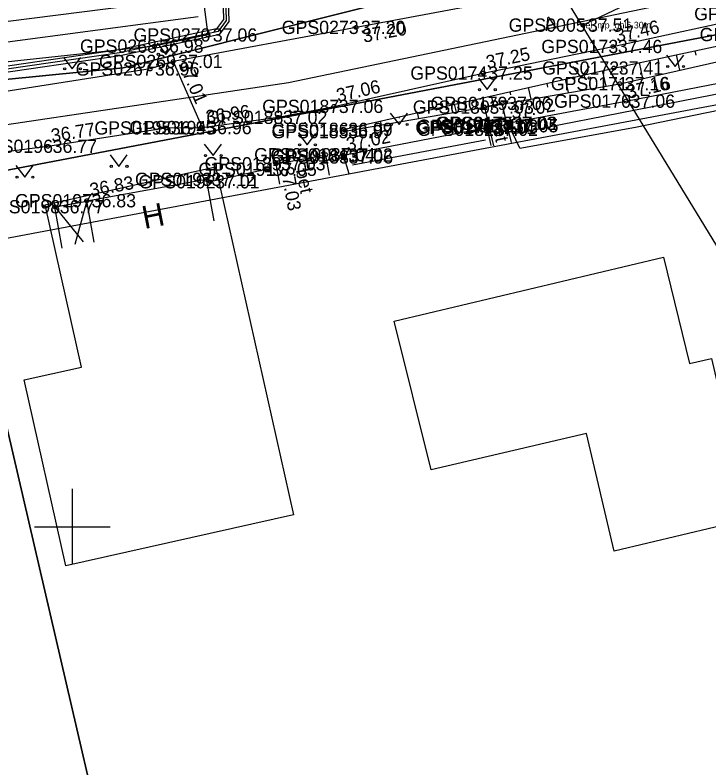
# Model space of a CAD drawing. Extents: x 626224 to 628280, y 6467750 to 6471135.
# Drawn here: x 627646.98 to 627683.58, y 6468587.27 to 6468627 of the extents above; entities that cross this region are included whole.
import ezdxf

# ---------------------------------------------------------------- set-up
doc = ezdxf.new("R2010")
doc.units = 0
for name, color, linetype in [('AED', 7, 'Continuous'), ('HALJASTUS', 7, 'Continuous'), ('HOONE', 7, 'Continuous'), ('Hoone Elu- või ühiskondlik hoone', 7, 'Continuous'), ('Hoone Kõrval- või tootmishoone', 7, 'Continuous'), ('HOONEDET', 7, 'Continuous'), ('KORGUS-EH2000', 7, 'Continuous'), ('KPKAABEL', 7, 'Continuous'), ('MAAMUDEL', 7, 'Continuous'), ('MOOTKORG-EH2000', 7, 'Continuous'), ('MOOTMPUNKT', 7, 'Continuous'), ('MOOTNR', 7, 'Continuous'), ('MOOTPIIR', 7, 'Continuous'), ('MPKAABEL', 7, 'Continuous'), ('MPOHULIIN', 7, 'Continuous'), ('PIIR', 7, 'Continuous'), ('RELJEEF', 7, 'Continuous'), ('TEE', 7, 'Continuous'), ('Tee Muu tee Kruuskate', 7, 'Continuous'), ('Tee Muu tee Püsikate', 7, 'Continuous'), ('VORK', 7, 'Continuous')]:
    doc.layers.add(name, color=color, linetype=linetype)

msp = doc.modelspace()

# ---------------------------------------------------------------- linework, layer by layer
at = {"layer": 'AED'}
for p, q in [((627671.829, 6468621.099), (627671.829, 6468620.849)), ((627671.829, 6468621.099), (627672.079, 6468621.099)), ((627672.079, 6468621.099), (627672.079, 6468620.849)), ((627672.91, 6468621.284), (627672.91, 6468621.034)), ((627672.91, 6468621.284), (627673.16, 6468621.284)), ((627672.91, 6468621.034), (627673.16, 6468621.034)), ((627673.16, 6468621.284), (627673.16, 6468621.034)), ((627671.829, 6468620.849), (627672.079, 6468620.849)), ((627664.186, 6468619.637), (627664.186, 6468619.387)), ((627664.186, 6468619.637), (627664.436, 6468619.637)), ((627664.436, 6468619.637), (627664.436, 6468619.387)), ((627664.186, 6468619.387), (627664.436, 6468619.387)), ((627660.291, 6468618.862), (627657.113, 6468618.168)), ((627660.166, 6468618.987), (627660.166, 6468618.737)), ((627660.166, 6468618.987), (627660.416, 6468618.987)), ((627660.166, 6468618.737), (627660.416, 6468618.737)), ((627660.416, 6468618.987), (627660.416, 6468618.737))]:
    msp.add_line(p, q, dxfattribs=at)
at = {"layer": 'HALJASTUS'}
for p, q in [((627637.187, 6468624.338), (627656.639, 6468626.929)), ((627654.473, 6468625.531), (627654.937, 6468624.925)), ((627654.937, 6468624.925), (627655.382, 6468625.531)), ((627649.535, 6468624.768), (627649.998, 6468624.161)), ((627649.998, 6468624.161), (627650.444, 6468624.768)), ((627681.34, 6468624.889), (627681.803, 6468624.282)), ((627681.803, 6468624.282), (627682.249, 6468624.889)), ((627676.376, 6468624.287), (627676.84, 6468623.68)), ((627676.84, 6468623.68), (627677.285, 6468624.287)), ((627671.416, 6468623.671), (627671.88, 6468623.064)), ((627671.88, 6468623.064), (627672.325, 6468623.671)), ((627666.768, 6468621.827), (627667.232, 6468621.22)), ((627667.232, 6468621.22), (627667.677, 6468621.827)), ((627661.927, 6468620.755), (627662.391, 6468620.148)), ((627662.391, 6468620.148), (627662.836, 6468620.755)), ((627664.781, 6468619.103), (627671.798, 6468620.423)), ((627656.96, 6468620.189), (627657.423, 6468619.582)), ((627657.423, 6468619.582), (627657.869, 6468620.189)), ((627651.992, 6468619.623), (627652.455, 6468619.016)), ((627652.455, 6468619.016), (627652.901, 6468619.623)), ((627647.024, 6468619.057), (627647.487, 6468618.45)), ((627647.487, 6468618.45), (627647.933, 6468619.057))]:
    msp.add_line(p, q, dxfattribs=at)
for points in [[(627636.336, 6468625.375), (627656.875, 6468628.003), (627657.149, 6468625.947), (627654.322, 6468625.361), (627643.674, 6468624.206), (627636.948, 6468623.11), (627636.336, 6468625.375)], [(627673.61, 6468619.969), (627672.976, 6468621.286), (627679.187, 6468622.456), (627687.969, 6468624.157), (627689.948, 6468620.551), (627692.796, 6468621.064), (627698.292, 6468613.159), (627705.989, 6468601.538), (627717.166, 6468585.678)], [(627716.572, 6468584.873), (627705.028, 6468601.396), (627692.406, 6468620.356), (627689.621, 6468619.759), (627687.703, 6468623.543), (627673.321, 6468620.739)], [(627673.61, 6468619.969), (627679.701, 6468621.092), (627687.315, 6468622.642), (627689.297, 6468618.889), (627691.61, 6468619.392), (627696.609, 6468612.017), (627704.309, 6468600.39), (627715.503, 6468584.506)], [(627664.609, 6468618.629), (627664.298, 6468619.611), (627671.869, 6468621.074), (627672.073, 6468620.112)]]:
    msp.add_lwpolyline(points, dxfattribs=at)
for centre in [(627654.536, 6468624.925), (627655.364, 6468624.925), (627649.597, 6468624.161), (627650.426, 6468624.161), (627681.402, 6468624.282), (627682.231, 6468624.282), (627676.439, 6468623.68), (627677.267, 6468623.68), (627671.479, 6468623.064), (627672.307, 6468623.064), (627666.831, 6468621.22), (627667.66, 6468621.22), (627661.99, 6468620.148), (627662.819, 6468620.148), (627657.022, 6468619.582), (627657.851, 6468619.582), (627652.054, 6468619.016), (627652.883, 6468619.016), (627647.086, 6468618.45), (627647.915, 6468618.45)]:
    msp.add_circle(centre, 0.055, dxfattribs=at)
at = {"layer": 'HOONE'}
for p, q in [((627650.758, 6468617.203), (627657.084, 6468618.331)), ((627657.474, 6468616.146), (627657.084, 6468618.331)), ((627649.076, 6468616.886), (627650.761, 6468617.186)), ((627651.147, 6468615.018), (627650.758, 6468617.203)), ((627649.466, 6468614.701), (627649.076, 6468616.886))]:
    msp.add_line(p, q, dxfattribs=at)
at = {"layer": 'Hoone Elu- või ühiskondlik hoone'}
msp.add_lwpolyline([(627678.585, 6468598.716), (627677.114, 6468604.925), (627668.925, 6468602.995), (627666.971, 6468610.855), (627681.171, 6468614.225), (627682.555, 6468608.606), (627683.705, 6468608.876), (627685.675, 6468600.395)], close=True, dxfattribs=at)
at = {"layer": 'Hoone Kõrval- või tootmishoone'}
msp.add_lwpolyline([(627661.667, 6468600.628), (627649.66, 6468597.941), (627647.466, 6468607.745), (627650.484, 6468608.42), (627648.567, 6468616.984), (627657.556, 6468618.996)], close=True, dxfattribs=at)
at = {"layer": 'HOONEDET'}
for p, q in [((627650.758, 6468617.203), (627650.14, 6468614.889)), ((627649.076, 6468616.886), (627650.564, 6468615.033))]:
    msp.add_line(p, q, dxfattribs=at)
at = {"layer": 'KORGUS-EH2000'}
for centre in [(627664.963, 6468626.349), (627678.512, 6468625.342), (627655.323, 6468624.553), (627671.677, 6468623.939), (627678.877, 6468623.378), (627663.795, 6468622.181), (627656.855, 6468621.064), (627672.976, 6468621.286), (627648.701, 6468620.075), (627664.298, 6468619.611), (627660.755, 6468619.153), (627657.273, 6468618.203), (627650.758, 6468617.203)]:
    msp.add_circle(centre, 0.1, dxfattribs=at)
at = {"layer": 'KPKAABEL'}
msp.add_lwpolyline([(627685.782, 6468640.643), (627682.599, 6468638.441), (627678.043, 6468635.809), (627672.046, 6468634.344), (627660.214, 6468631.662), (627657.997, 6468630.954), (627658.117, 6468626.708), (627657.689, 6468626.13), (627652.495, 6468625.008), (627640.455, 6468623.259), (627628.481, 6468622.246), (627623.048, 6468622.007), (627612.632, 6468622.516), (627609.034, 6468622.858), (627605.474, 6468623.034), (627601.854, 6468622.409), (627599.956, 6468622.4), (627599.775, 6468623.347)], dxfattribs=at)
at = {"layer": 'MOOTMPUNKT'}
for centre in [(627664.963, 6468626.349), (627676.933, 6468626.469), (627676.933, 6468626.469), (627657.149, 6468625.947), (627654.322, 6468625.361), (627678.512, 6468625.342), (627655.323, 6468624.553), (627654.099, 6468624.153), (627678.559, 6468624.205), (627671.677, 6468623.939), (627678.877, 6468623.378), (627663.795, 6468622.181), (627671.739, 6468622.144), (627672.671, 6468622.34), (627679.187, 6468622.456), (627660.849, 6468621.603), (627654.943, 6468621.043), (627656.855, 6468621.064), (627664.293, 6468620.969), (627671.869, 6468621.074), (627671.954, 6468620.974), (627671.964, 6468621.133), (627672.925, 6468621.283), (627672.976, 6468621.286), (627673.035, 6468621.159), (627664.284, 6468620.85), (627648.701, 6468620.075), (627663.372, 6468619.631), (627664.298, 6468619.611), (627664.311, 6468619.512), (627660.755, 6468619.153), (627660.291, 6468618.862), (627657.084, 6468618.331), (627657.273, 6468618.203), (627650.758, 6468617.203), (627649.076, 6468616.886)]:
    msp.add_circle(centre, 0.1, dxfattribs=at)
at = {"layer": 'MOOTPIIR'}
msp.add_lwpolyline([(627644.92, 6468614.927), (627687.389, 6468622.904), (627689.377, 6468619.311), (627692.038, 6468619.76), (627702.956, 6468602.021), (627695.606, 6468595.477), (627701.992, 6468581.333), (627711.232, 6468581.738), (627717.166, 6468585.678), (627720.646, 6468589.364)], dxfattribs=at)
at = {"layer": 'MPKAABEL'}
for points in [[(627685.699, 6468640.768), (627682.519, 6468638.568), (627677.987, 6468635.95), (627672.012, 6468634.49), (627660.175, 6468631.807), (627657.844, 6468631.063), (627657.966, 6468626.756), (627657.602, 6468626.265), (627652.468, 6468625.156), (627640.438, 6468623.408), (627628.471, 6468622.396), (627623.048, 6468622.157), (627612.643, 6468622.666), (627609.045, 6468623.008), (627605.465, 6468623.185), (627601.841, 6468622.559), (627601.344, 6468627.176), (627599.992, 6468627.142), (627599.551, 6468626.364)], [(627599.73, 6468626.375), (627600.081, 6468626.994), (627601.209, 6468627.023), (627601.759, 6468622.259), (627605.483, 6468622.883), (627609.023, 6468622.708), (627612.621, 6468622.366), (627623.048, 6468621.857), (627628.491, 6468622.096), (627640.472, 6468623.11), (627652.522, 6468624.86), (627657.776, 6468625.995), (627658.268, 6468626.66), (627658.15, 6468630.845), (627660.253, 6468631.517), (627672.08, 6468634.198), (627673.058, 6468632.736)], [(627685.401, 6468627.702), (627679.495, 6468627.683), (627676.897, 6468626.445)]]:
    msp.add_lwpolyline(points, dxfattribs=at)
at = {"layer": 'MPOHULIIN'}
for points in [[(627679.915, 6468621.5), (627673.058, 6468632.736), (627672.71, 6468633.307)], [(627695.728, 6468595.585), (627679.915, 6468621.5)]]:
    msp.add_lwpolyline(points, dxfattribs=at)
at = {"layer": 'PIIR'}
for points in [[(627654.85, 6468663.52), (627663.66, 6468662.2), (627686.69, 6468632.75), (627684.35, 6468632.16), (627652.69, 6468624.22), (627623.24, 6468621.3), (627605.69, 6468621.95), (627588.94, 6468620.18), (627586.23, 6468625.97), (627596.31, 6468635.4), (627619.6, 6468659.76), (627624.98, 6468665.39), (627633.24, 6468674.95), (627637.73, 6468680.5), (627640.48, 6468683.65), (627644.86, 6468680.34)], [(627746.91, 6468541.23), (627666.94, 6468517.08), (627653, 6468577.43), (627643.52, 6468618.24), (627688.18, 6468626.77)], [(627599.49, 6468616.8), (627643.52, 6468618.24), (627653, 6468577.43), (627666.94, 6468517.08), (627608.44, 6468499.25), (627602.15, 6468514.88), (627588.44, 6468509.87), (627563.73, 6468583.75), (627555.29, 6468612.05)]]:
    msp.add_lwpolyline(points, close=True, dxfattribs=at)
msp.add_lwpolyline([(627401.5, 6468603.97), (627489.68, 6468613.41), (627577.55, 6468622.81), (627581.38, 6468622.85), (627583, 6468623.57), (627584.27, 6468624.13), (627586.23, 6468625.97), (627588.94, 6468620.18), (627605.69, 6468621.95), (627623.24, 6468621.3), (627652.69, 6468624.22), (627684.35, 6468632.16), (627688.18, 6468626.77), (627643.52, 6468618.24), (627599.49, 6468616.8), (627555.29, 6468612.05), (627411.34, 6468595.13)], dxfattribs=at)
at = {"layer": 'RELJEEF'}
for p, q in [((627682.835, 6468625.114), (627682.886, 6468624.874)), ((627680.878, 6468624.698), (627680.931, 6468624.45)), ((627681.856, 6468624.906), (627682.03, 6468624.092)), ((627678.922, 6468624.282), (627678.977, 6468624.026)), ((627679.9, 6468624.49), (627680.079, 6468623.65)), ((627676.971, 6468623.844), (627677.023, 6468623.614)), ((627677.946, 6468624.066), (627678.131, 6468623.249)), ((627675.995, 6468623.623), (627676.158, 6468622.907)), ((627674.045, 6468623.181), (627674.185, 6468622.565)), ((627675.02, 6468623.402), (627675.065, 6468623.202)), ((627672.094, 6468622.738), (627672.211, 6468622.223)), ((627673.07, 6468622.96), (627673.108, 6468622.79)), ((627670.144, 6468622.296), (627670.238, 6468621.882)), ((627671.119, 6468622.517), (627671.151, 6468622.378)), ((627668.194, 6468621.854), (627668.265, 6468621.54)), ((627669.169, 6468622.075), (627669.194, 6468621.966)), ((627667.218, 6468621.633), (627667.236, 6468621.553)), ((627665.268, 6468621.19), (627665.279, 6468621.141)), ((627666.243, 6468621.411), (627666.291, 6468621.198)), ((627664.293, 6468620.969), (627664.318, 6468620.856))]:
    msp.add_line(p, q, dxfattribs=at)
for points in [[(627664.293, 6468620.969), (627678.559, 6468624.205), (627686.866, 6468625.972), (627692.626, 6468627.53), (627694.391, 6468627.395), (627696.02, 6468626.757), (627697.766, 6468625.488), (627704.517, 6468617.101), (627712.652, 6468604.661), (627723.007, 6468591.238)], [(627664.284, 6468620.85), (627678.877, 6468623.378), (627691.199, 6468626.166), (627693.024, 6468626.089), (627694.96, 6468625.086), (627696.853, 6468623.559), (627702.288, 6468615.532), (627710.843, 6468603.567), (627720.646, 6468589.364)]]:
    msp.add_lwpolyline(points, dxfattribs=at)
at = {"layer": 'TEE'}
for p, q in [((627663.568, 6468618.555), (627663.372, 6468619.631)), ((627660.951, 6468618.078), (627660.755, 6468619.153))]:
    msp.add_line(p, q, dxfattribs=at)
for points in [[(627691.556, 6468636.216), (627691.411, 6468633.572), (627690.377, 6468632.362), (627688.302, 6468631.311), (627683.705, 6468630.285), (627675.534, 6468628.326), (627664.963, 6468626.349), (627655.323, 6468624.553), (627656.855, 6468621.064), (627660.849, 6468621.603), (627663.795, 6468622.181), (627671.677, 6468623.939), (627678.512, 6468625.342), (627686.437, 6468627.071), (627694.212, 6468628.779), (627696.498, 6468628.635), (627697.947, 6468628.287), (627705.762, 6468618.126), (627714.785, 6468606.184), (627724.497, 6468592.392)], [(627655.323, 6468624.553), (627654.099, 6468624.153), (627644.239, 6468622.621), (627634.78, 6468621.504), (627626.983, 6468620.991), (627620.731, 6468620.942), (627612.855, 6468621.244), (627605.321, 6468621.364)], [(627673.157, 6468620.276), (627672.925, 6468621.283), (627672.671, 6468622.34), (627671.739, 6468622.144), (627671.964, 6468621.133), (627672.206, 6468620.091)], [(627605.451, 6468618.323), (627611.844, 6468618.339), (627612.555, 6468616.606), (627613.007, 6468613.838), (627616.056, 6468613.833), (627615.95, 6468616.377), (627616.311, 6468617.523), (627617.098, 6468617.911), (627625.292, 6468617.768), (627631.755, 6468618.128), (627635.301, 6468618.359), (627643.867, 6468619.473), (627648.701, 6468620.075), (627654.943, 6468621.043), (627656.855, 6468621.064)], [(627660.755, 6468619.153), (627663.372, 6468619.631)]]:
    msp.add_lwpolyline(points, dxfattribs=at)
at = {"layer": 'Tee Muu tee Kruuskate'}
msp.add_lwpolyline([(627655.281, 6468622.513), (627643.219, 6468620.707), (627634.046, 6468619.94), (627621.905, 6468619.252), (627606.783, 6468619.17), (627583.198, 6468617.485), (627569.985, 6468616.221), (627554.678, 6468614.391), (627502.881, 6468608.768), (627472.157, 6468604.735), (627458.252, 6468603.133), (627409.627, 6468597.894), (627406.06, 6468597.51)], dxfattribs=at)
at = {"layer": 'Tee Muu tee Püsikate'}
msp.add_lwpolyline([(627700.902, 6468634.138), (627694.794, 6468631.457), (627685.552, 6468628.47), (627661.394, 6468623.428), (627655.281, 6468622.513)], dxfattribs=at)
at = {"layer": 'VORK'}
for p, q in [((627650, 6468602), (627650, 6468598)), ((627648, 6468600), (627652, 6468600))]:
    msp.add_line(p, q, dxfattribs=at)

# ---------------------------------------------------------------- texts
at = {"layer": 'HOONE'}
msp.add_text('H', height=1.2, rotation=11.209, dxfattribs=at).set_placement((627653.807, 6468615.706))
at = {"layer": 'KORGUS-EH2000'}
for s, rotation, p in [(' 37.20', 10.6887, (627665.124, 6468625.489)), (' 37.46', 12.3056, (627678.475, 6468625.513)), (' 37.25', 11.6054, (627671.642, 6468624.11)), (' 37.01', 293.7011, (627655.484, 6468624.623)), (' 37.06', 12.5685, (627663.757, 6468622.352)), (' 37.16', 12.75, (627679.07, 6468622.525)), (' 36.96', 7.6864, (627656.831, 6468621.237)), (' 37.02', 10.6662, (627672.944, 6468621.458)), (' 36.77', 8.8198, (627648.674, 6468620.248)), (' 37.02', 10.9372, (627664.265, 6468619.782)), (' 37.03', 280.3357, (627660.927, 6468619.185)), (' 36.83', 10.1082, (627650.727, 6468617.375))]:
    msp.add_text(s, height=0.7, rotation=rotation, dxfattribs=at).set_placement(p)
msp.add_text(' 37.01', height=0.7, dxfattribs=at).set_placement((627657.273, 6468617.853))
at = {"layer": 'MAAMUDEL'}
msp.add_text(' el_mp_ohl6.30m', height=0.35, dxfattribs=at).set_placement((627676.933, 6468626.294))
at = {"layer": 'MOOTKORG-EH2000'}
for s, p in [(' 37.20', (627664.963, 6468625.999)), (' 37.51', (627676.933, 6468626.119)), (' 37.06', (627657.149, 6468625.597)), (' 36.98', (627654.322, 6468625.011)), (' 37.46', (627678.512, 6468624.992)), (' 37.01', (627655.323, 6468624.203)), (' 36.96', (627654.099, 6468623.803)), (' 37.25', (627671.677, 6468623.589)), (' 37.41', (627678.559, 6468623.855)), (' 37.16', (627678.877, 6468623.028)), (' 37.06', (627672.671, 6468621.99)), (' 37.06', (627679.187, 6468622.106)), (' 37.06', (627663.795, 6468621.831)), (' 37.03', (627671.739, 6468621.794)), (' 37.02', (627660.849, 6468621.253)), (' 37.01', (627671.869, 6468620.724)), (' 37.03', (627671.964, 6468620.783)), (' 37.03', (627672.925, 6468620.933)), (' 37.02', (627672.976, 6468620.936)), (' 37.05', (627673.035, 6468620.809)), (' 36.95', (627654.943, 6468620.693)), (' 36.96', (627656.855, 6468620.714)), (' 36.97', (627664.284, 6468620.5)), (' 36.99', (627664.293, 6468620.619)), (' 37.02', (627671.954, 6468620.624)), (' 36.77', (627648.701, 6468619.725)), (' 37.04', (627663.372, 6468619.281)), (' 37.02', (627664.298, 6468619.261)), (' 37.06', (627664.311, 6468619.162)), (' 37.03', (627660.755, 6468618.803)), (' 37.05', (627660.291, 6468618.512)), (' 37.12', (627657.084, 6468617.981)), (' 37.01', (627657.273, 6468617.853)), (' 36.83', (627650.758, 6468616.853)), (' 36.77', (627649.076, 6468616.536))]:
    msp.add_text(s, height=0.7, dxfattribs=at).set_placement(p)
at = {"layer": 'MOOTNR'}
for s, p in [('GPS0161 ', (627682.797, 6468626.721)), ('GPS0273 ', (627661.043, 6468625.999)), ('GPS0005 ', (627673.014, 6468626.119)), ('GPS0005 ', (627673.014, 6468626.119)), ('GPS0270 ', (627653.229, 6468625.597)), ('GPS0160 ', (627683.087, 6468625.622)), ('GPS0268 ', (627650.403, 6468625.011)), ('GPS0173 ', (627674.733, 6468624.992)), ('GPS0269 ', (627651.404, 6468624.203)), ('GPS0267 ', (627650.179, 6468623.803)), ('GPS0174 ', (627667.828, 6468623.589)), ('GPS0172 ', (627674.779, 6468623.855)), ('GPS0171 ', (627675.237, 6468623.028)), ('GPS0179 ', (627668.891, 6468621.99)), ('GPS0170 ', (627675.407, 6468622.106)), ('GPS0187 ', (627660.015, 6468621.831)), ('GPS0180 ', (627667.959, 6468621.794)), ('GPS0188 ', (627657.07, 6468621.253)), ('GPS0176 ', (627668.09, 6468620.724)), ('GPS0177 ', (627668.184, 6468620.783)), ('GPS0178 ', (627669.145, 6468620.933)), ('GPS0175 ', (627669.196, 6468620.936)), ('GPS0181 ', (627669.395, 6468620.809)), ('GPS0195 ', (627651.163, 6468620.693)), ('GPS0194 ', (627653.005, 6468620.714)), ('GPS0185 ', (627660.504, 6468620.5)), ('GPS0186 ', (627660.513, 6468620.619)), ('GPS0182 ', (627668.174, 6468620.624)), ('GPS0196 ', (627644.921, 6468619.725)), ('GPS0190 ', (627659.592, 6468619.281)), ('GPS0184 ', (627660.448, 6468619.261)), ('GPS0183 ', (627660.531, 6468619.162)), ('GPS0189 ', (627656.975, 6468618.803)), ('GPS0191 ', (627656.651, 6468618.512)), ('GPS0193 ', (627653.304, 6468617.981)), ('GPS0192 ', (627653.494, 6468617.853)), ('GPS0197 ', (627646.978, 6468616.853)), ('GPS0198 ', (627645.297, 6468616.536))]:
    msp.add_text(s, height=0.7, dxfattribs=at).set_placement(p)
at = {"layer": 'TEE'}
for s, rotation, p in [('A', 14.1471, (627674.964, 6468626.151)), ('bet', 281.7481, (627672.078, 6468621.523)), ('bet', 281.7481, (627661.781, 6468618.812))]:
    msp.add_text(s, height=0.7, rotation=rotation, dxfattribs=at).set_placement(p)

doc.saveas('drawing.dxf')
